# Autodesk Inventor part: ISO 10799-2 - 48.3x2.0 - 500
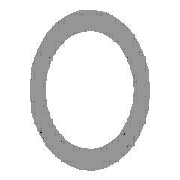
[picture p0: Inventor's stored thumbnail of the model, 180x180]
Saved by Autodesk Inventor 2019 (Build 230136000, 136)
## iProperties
IsCustomPart: 1
Created: 2018-07
Part Number: ISO 10799-2 - 48.3x2.0 - 500
Material: Acier, doux
Description: Aciers de construction - Coupes creuses profilées formées à froid, soudées
Document SubType Name: Modeling
Standard: ISO
Designer: Fabian Perrée
Standard Revision: First edition 2011-09-15
Standards Organization: ISO
Language: fr-FR
Size Designation: 48.3x2.0
Categories: <MemberInstance><Categories><Category DisplayName="Profilés" InternalName="089c4875-fa83-4c05-b084-43b9cc11f5ed" Mnemonic="GRDR"><CategoryParameter DisplayName=
Stock Number: 48.3x2.0
Density: 7.85 g/cm^3
Appearance: Semi-poli
Mass: 1103.72 g
Surface Area: 1414.8 cm^2
Volume: 140.601 cm^3
_CCFamilyMember: 14
_CCFamilyDisplayName: ISO 10799-2 (Profils creux circulaires - Formés à froid) - Aciers de construction - Coupes creuses profilées formées à froid, soudées
_FrameMemberDoc: Frame Member File
_Version: 15.0.0
_GetPNFromCC: 1
G_L: 500,000 mm
G_W: 48,300 mm
G_H: 48,300 mm
+AB852084-64D8-4805-9BA0-F1D26D228743+DETAILDECOUPE1: Grugeage
Author: Fabian Perrée
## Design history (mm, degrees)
node "Plan de départ"
node "Plan de fin"
sketch "Esquisse"
  geometry: C1 r 22.15 at (0, 0); C2 r 24.15 at (0, 0); 2 further points
  constraints: 3 coincident, 2 centre point
  dimensions: "d0" = 48.3 diameter of C2 (= G_H); "d1" = 2 radial gap between concentric circles of C2 C1 (= G_T)
extrude "Corps" new body sketch "Esquisse" stored distance "d2" = 500 (= G_L); taper "d3" = 0 deg
node "Driven Length"
  sketch "Sketch3"
    geometry: L1 (0, 0)-(10, 0) reference
    constraints: 2 end point, 1 horizontal
  workplane "Work Plane3"
  sketch "Sketch4"
    geometry: L1 (-2, 0)-(12, 0) reference; L2 (-2, 500)-(12, 500) reference
    dimensions: "d7" = 500 distance between parallel lines of L1 L2 (derived)
body "Solid1"
feature "Sculpter1"
feature "Combiner1"
body "Srf5"
body "Srf6"
node "Solide3"
feature "Surface1"
body "Srf4"
feature "Carreau délimité3" dims "d12" = 5, "d13" = 0
feature "Carreau délimité4" dims "d14" = 5, "d15" = 0
other parameters: "G_H" = 48.3 [user parameter; used in 1 equation term], "G_T" = 2 [user parameter; used in 1 equation term], "G_L" = 500 (= d7) [user parameter; used in 1 equation term], "G_OFFSET_START" = 0 [user parameter; used in 1 equation term], "G_OFFSET_END" = 0 [user parameter; used in 1 equation term], "d4" = 0 (computed from G_OFFSET_START), "d5" = 500 (= G_OFFSET_END + B_L), "B_L" = 500 [user parameter; used in 1 equation term], "d6" = 90 deg, "MAS" = 0.228 [user parameter]
